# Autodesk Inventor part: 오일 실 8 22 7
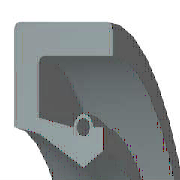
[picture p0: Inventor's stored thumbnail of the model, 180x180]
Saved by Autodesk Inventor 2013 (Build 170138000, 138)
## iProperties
IsCustomPart: 1
Created: 2012-02
Part Number: 오일 실 8 22 7
Material: 고무
Description: 오일-실
Document SubType Name: Modeling
Standard: KS B 2804
Designer: test
Standards Organization: KS
Language: ko-KR
Size Designation: S - 8 22 7
Categories: <MemberInstance><Categories><Category DisplayName="샤프트 부품" InternalName="7f7aeb1f-a693-4053-b835-cee3144e0d98" Mnemonic="SHFT"><Category DisplayName="실링" Intern
Density: 0.93 g/cm^3
Author: test
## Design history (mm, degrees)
revolve "본체" stored, may be unused: angle "d17" = 90 deg
revolve "스프링1" stored, may be unused: angle "d18" = 90 deg
body "Solid1"
sketch "스케치1"
  geometry: L1 (0, 11)-(7, 11); L2 (7, 11)-(7, 9.75); L3 (7, 9.75)-(1.75, 9.75); L4 (0, 11)-(0, 6.1); L5 (0, 6.1)-(1.75, 5.75); L6 (1.75, 5.75)-(4.9, 4); L7 (4.9, 4)-(0, 4); L8 (6.3, 4.875)-(6.3, 6.1); L9 (0, 0)-(9.586, 0) reference; L10 (4.9, 4)-(6.3, 4.875); L11 (0, 18)-(0, -3) reference; L12 (-1.917, 0)-(11.503, 0) reference; L13 (4.2, 6.1)-(1.75, 6.59); L14 (1.75, 6.59)-(1.75, 9.75); L15 (6.3, 6.1)-(5.6, 6.1); C1 r 0.455 at (4.9, 6.1); A1 r 0.7 centre (4.9, 6.1) between (5.6, 6.1) and (4.2, 6.1)
  constraints: 26 end point, 5 horizontal alignment, 4 perpendicular, 2 centre point, 2 collinear, 2 horizontal, 2 parallel, 2 point on circle, 2 point on line, 2 vertical alignment, 1 coincident
  dimensions: "d0" = 22 diameter of L1 L9 (= SD2); "d1" = 9.75 diameter of L8.start L9 (= ABDM); "d2" = 1.25 distance of L1.end L2.end (computed from SD); "d3" = 0.91 diameter of C1 (= SPDI); "d4" = 1.4 diameter of A1 (= SPDA); "d5" = 8 diameter of L6.end L9 (= NND); "d6" = 11.5 diameter of L5.end L9 (= TKDM); "d7" = 12.2 diameter of L4.end L9 (= HLDM); "d8" = 4.9 distance from line of C1.centre L4 (= SPDST); "d9" = 6.3 distance between parallel lines of L8 L4 (= SDI); "d10" = 7 distance between parallel lines of L2 L4 (= SWDT); "d12" = 1.75 distance between parallel lines of L14 L4 (= SD)
fillet "모깎기1" dims "d11" = 0.3 (= RR)
other parameters: "SD2" = 22 [user parameter; used in 1 equation term], "SWDT" = 7 [user parameter; used in 1 equation term], "RR" = 0.3 [user parameter; used in 1 equation term], "SD" = 1.75 [user parameter; used in 2 equation terms], "NND" = 8 [user parameter; used in 1 equation term], "SPDA" = 1.4 [user parameter; used in 1 equation term], "SPDI" = 0.91 [user parameter; used in 1 equation term], "TKDM" = 11.5 [user parameter; used in 1 equation term], "HLDM" = 12.2 [user parameter; used in 1 equation term], "ABDM" = 9.75 [user parameter; used in 1 equation term], "SDI" = 6.3 [user parameter; used in 1 equation term], "SPDST" = 4.9 [user parameter; used in 1 equation term], "d13" = 0, "d14" = 0, "d15" = 0, "LAB" = 0.35 [user parameter]
